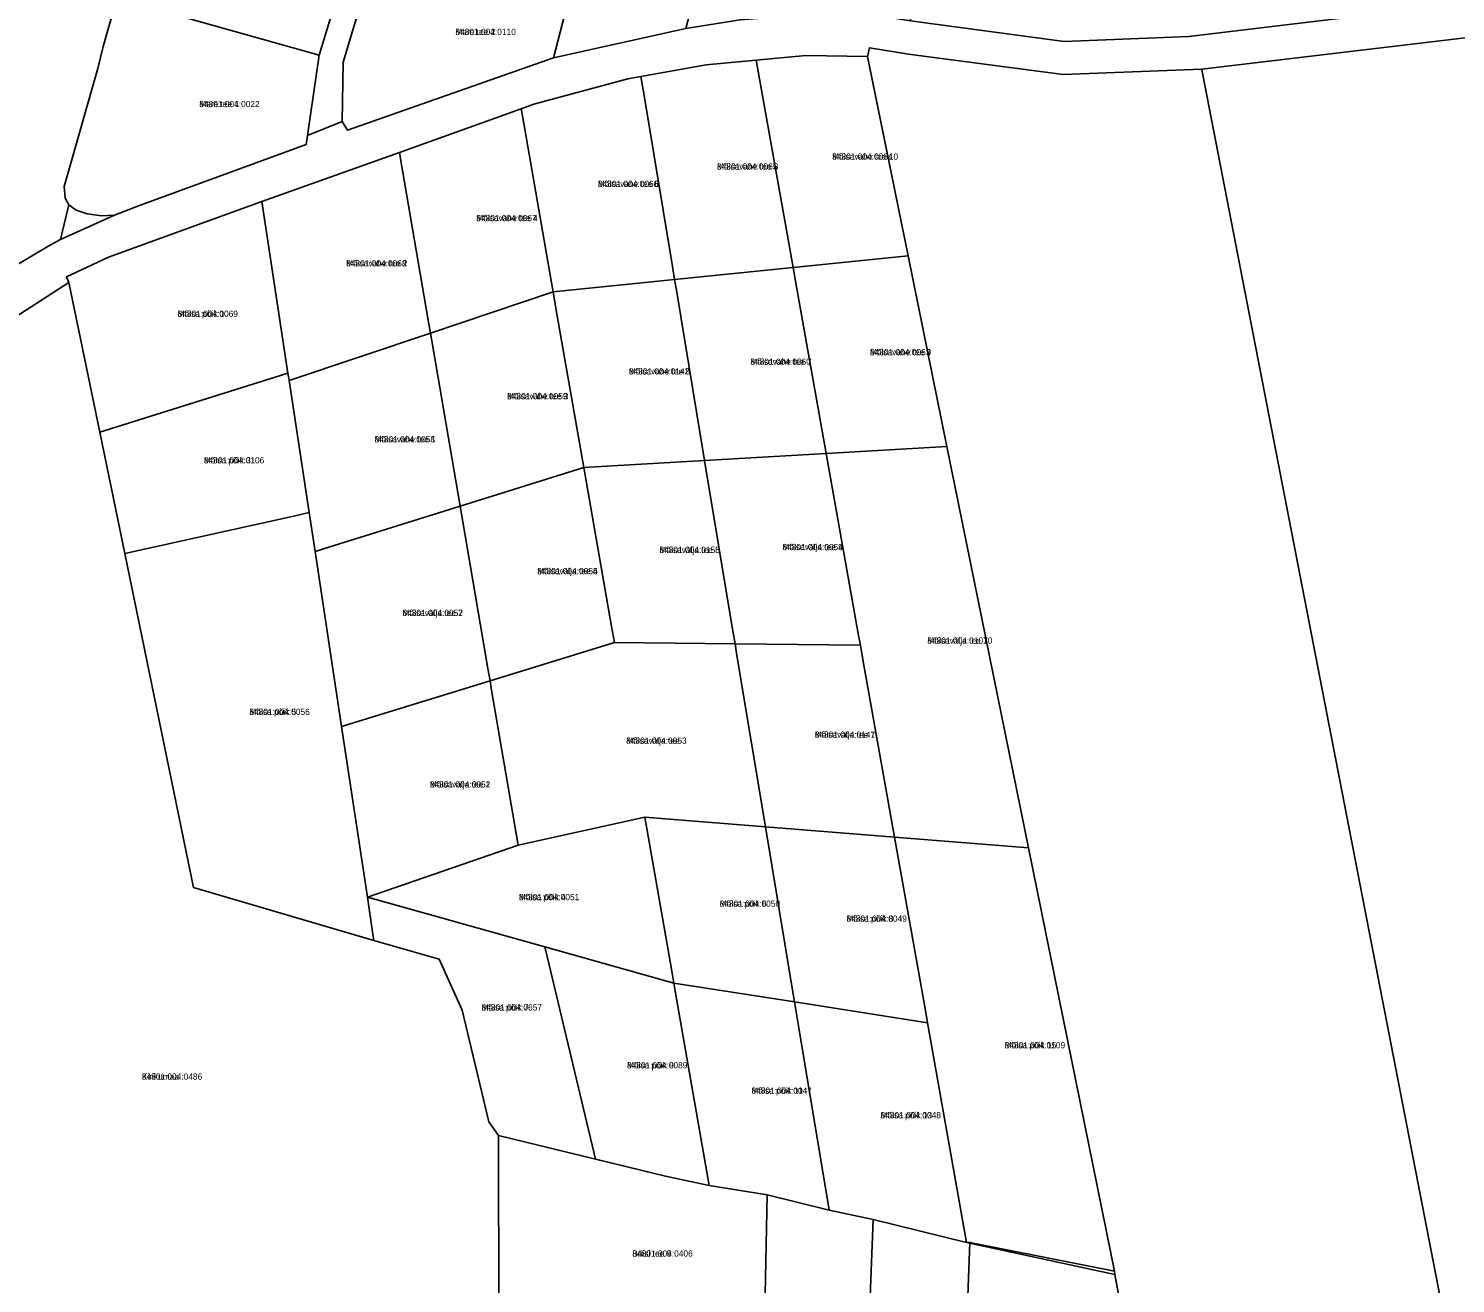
# Model space of a CAD drawing. Extents: x 520985 to 542706, y 6413723 to 6468993.
# Drawn here: x 528345 to 528687.6, y 6455911.2 to 6456212.7 of the extents above; entities that cross this region are included whole.
import ezdxf

# ---------------------------------------------------------------- set-up
doc = ezdxf.new("R2010")
doc.units = 0
for name, color, linetype in [('L_AADRESS', 7, 'Continuous'), ('PIIR', 7, 'Continuous'), ('TUNNUS', 7, 'Continuous')]:
    doc.layers.add(name, color=color, linetype=linetype)

msp = doc.modelspace()

# ---------------------------------------------------------------- linework, layer by layer
at = {"layer": 'PIIR'}
for points in [[(528556.88, 6456216.98), (528558.68, 6456259.93), (528619.9, 6456257.99), (528624.94, 6456257.83), (528679.22, 6456448.72), (528737.44, 6456454.64), (528782.62, 6456232.25), (528783.08, 6456229.98), (528623.6, 6456210.72), (528593.64, 6456209.59), (528556.78, 6456214.48)], [(528516.48, 6456264.57), (528503.27, 6456214.54), (528502.79, 6456212.71), (528471.03, 6456205.61), (528471.51, 6456207.45), (528474.91, 6456220.55), (528481.64, 6456246.71), (528488.41, 6456272.88)], [(528366.21, 6456219.91), (528372.01, 6456242.17), (528373.83, 6456241.69), (528421.37, 6456228.24), (528414.79, 6456206.25), (528367.66, 6456219.53)], [(528474.91, 6456220.55), (528471.51, 6456207.45), (528471.03, 6456205.61), (528421.58, 6456188.22), (528420.26, 6456190.35), (528420.55, 6456204.62), (528429.36, 6456234)], [(528367.66, 6456219.53), (528414.79, 6456206.25), (528411.94, 6456186.98), (528411.61, 6456184.79), (528371.6, 6456170.12), (528365.61, 6456167.8), (528362.48, 6456167.65), (528359.04, 6456168.19), (528356.38, 6456169.07), (528354.63, 6456170.34), (528353.76, 6456171.88), (528353.55, 6456174.72), (528361.65, 6456203.1), (528362.91, 6456208.35), (528366.21, 6456219.91)], [(528704.77, 6456212.22), (528705.38, 6456209.19), (528941.94, 6455028.97), (528863.78, 6455010.13), (528766.34, 6455483.52), (528702.03, 6455814.63), (528626.9, 6456201.95), (528626.71, 6456202.92)], [(528499.59, 6456155.52), (528492.86, 6456196.14), (528492.03, 6456201.17), (528507.69, 6456203.91), (528519.72, 6456205.07), (528528.18, 6456157.49), (528528.58, 6456155.26), (528500.12, 6456152.4)], [(528528.18, 6456157.49), (528519.72, 6456205.07), (528531.66, 6456206.22), (528546.44, 6456205.97), (528546.76, 6456204.37), (528556.18, 6456158.05), (528528.58, 6456155.26)], [(528470.4, 6456152.55), (528463.56, 6456191.69), (528463.26, 6456193.41), (528466.32, 6456194.49), (528488.85, 6456200.62), (528492.03, 6456201.17), (528492.86, 6456196.14), (528499.59, 6456155.52), (528500.12, 6456152.4), (528470.93, 6456149.45)], [(528440.94, 6456142.63), (528434.31, 6456181.37), (528434.05, 6456182.92), (528463.26, 6456193.41), (528463.56, 6456191.69), (528470.4, 6456152.55), (528470.93, 6456149.45), (528441.48, 6456139.52)], [(528407.26, 6456129.84), (528401, 6456171.1), (528434.05, 6456182.92), (528434.31, 6456181.37), (528440.94, 6456142.63), (528441.48, 6456139.52), (528407.54, 6456128.08)], [(528354.05, 6456153.01), (528364.19, 6456157.74), (528401, 6456171.1), (528407.26, 6456129.84), (528404.18, 6456128.89), (528362.06, 6456115.69), (528354.61, 6456151.67)], [(528529.16, 6456152.01), (528528.58, 6456155.26), (528556.18, 6456158.05), (528565.46, 6456112.29), (528536.53, 6456110.6)], [(528500.62, 6456149.36), (528500.12, 6456152.4), (528528.58, 6456155.26), (528529.16, 6456152.01), (528536.53, 6456110.6), (528507.33, 6456108.9)], [(528354.61, 6456151.67), (528362.06, 6456115.69), (528368.09, 6456086.54), (528384.57, 6456006.27), (528427.91, 6455993.57), (528434.62, 6455991.69), (528443.55, 6455989.09), (528449.1, 6455976.87), (528455.47, 6455949.99), (528457.82, 6455946.69), (528457.9, 6455903.07), (528449.98, 6455902.56), (528432.93, 6455887.74), (528435.26, 6455864.87), (528344.52, 6455848.73), (528318.55, 6455941.07), (528290.8, 6455984.15), (528286.46, 6456012.85), (528297.35, 6456077.01), (528306.62, 6456113.22), (528332.88, 6456137.64)], [(528471.71, 6456145.01), (528470.93, 6456149.45), (528500.12, 6456152.4), (528500.62, 6456149.36), (528507.33, 6456108.9), (528478.32, 6456107.2)], [(528441.79, 6456137.67), (528441.48, 6456139.52), (528470.93, 6456149.45), (528471.71, 6456145.01), (528478.32, 6456107.2), (528448.6, 6456097.91)], [(528413.77, 6456087), (528412.35, 6456096.36), (528407.54, 6456128.08), (528441.48, 6456139.52), (528441.79, 6456137.67), (528448.6, 6456097.91), (528417.1, 6456088.05)], [(528362.06, 6456115.69), (528404.18, 6456128.89), (528407.26, 6456129.84), (528407.54, 6456128.08), (528412.35, 6456096.36), (528409.03, 6456095.63), (528368.09, 6456086.54)], [(528514.13, 6456067.88), (528507.33, 6456108.9), (528536.53, 6456110.6), (528544.31, 6456066.81), (528544.72, 6456064.49), (528514.63, 6456064.85)], [(528545.34, 6456061.06), (528544.72, 6456064.49), (528544.31, 6456066.81), (528536.53, 6456110.6), (528565.46, 6456112.29), (528585.06, 6456015.8), (528552.93, 6456018.38)], [(528455.28, 6456058.93), (528448.6, 6456097.91), (528478.32, 6456107.2), (528485, 6456068.97), (528485.66, 6456065.19), (528455.79, 6456055.96)], [(528485, 6456068.97), (528478.32, 6456107.2), (528507.33, 6456108.9), (528514.13, 6456067.88), (528514.63, 6456064.85), (528485.66, 6456065.19)], [(528368.09, 6456086.54), (528409.03, 6456095.63), (528412.35, 6456096.36), (528413.77, 6456087), (528420.15, 6456044.96), (528426.37, 6456003.99), (528427.59, 6455995.69), (528427.91, 6455993.57), (528384.57, 6456006.27)], [(528413.77, 6456087), (528417.1, 6456088.05), (528448.6, 6456097.91), (528455.28, 6456058.93), (528455.79, 6456055.96), (528420.15, 6456044.96)], [(528462.55, 6456016.49), (528456.17, 6456053.75), (528455.79, 6456055.96), (528485.66, 6456065.19), (528514.63, 6456064.85), (528515.09, 6456062.08), (528521.92, 6456020.89), (528492.99, 6456023.21)], [(528515.09, 6456062.08), (528514.63, 6456064.85), (528544.72, 6456064.49), (528545.34, 6456061.06), (528552.93, 6456018.38), (528521.92, 6456020.89)], [(528420.15, 6456044.96), (528455.79, 6456055.96), (528456.17, 6456053.75), (528462.55, 6456016.49), (528426.37, 6456003.99)], [(528426.37, 6456003.99), (528462.55, 6456016.49), (528492.99, 6456023.21), (528499.36, 6455986.67), (528499.96, 6455983.31), (528468.94, 6455992.03)], [(528499.36, 6455986.67), (528492.99, 6456023.21), (528521.92, 6456020.89), (528528.42, 6455981.62), (528528.9, 6455978.8), (528499.96, 6455983.31)], [(528528.42, 6455981.62), (528521.92, 6456020.89), (528552.93, 6456018.38), (528560.33, 6455976.76), (528560.86, 6455973.82), (528528.9, 6455978.8)], [(528561.42, 6455970.65), (528560.86, 6455973.82), (528560.33, 6455976.76), (528552.93, 6456018.38), (528585.06, 6456015.8), (528605.71, 6455914.15), (528605.84, 6455913.35), (528570.24, 6455921.03)], [(528427.91, 6455993.57), (528427.59, 6455995.69), (528426.37, 6456003.99), (528468.94, 6455992.03), (528469.96, 6455987.75), (528481.15, 6455941.03), (528457.82, 6455946.69), (528455.47, 6455949.99), (528449.1, 6455976.87), (528443.55, 6455989.09), (528434.62, 6455991.69)], [(528469.96, 6455987.75), (528468.94, 6455992.03), (528499.96, 6455983.31), (528500.52, 6455980.06), (528508.43, 6455934.75), (528497.9, 6455936.96), (528481.15, 6455941.03)], [(528500.52, 6455980.06), (528499.96, 6455983.31), (528528.9, 6455978.8), (528529.85, 6455973.07), (528537.2, 6455928.81), (528522.34, 6455932.47), (528508.43, 6455934.75)], [(528529.85, 6455973.07), (528528.9, 6455978.8), (528560.86, 6455973.82), (528561.42, 6455970.65), (528570.24, 6455921.03), (528547.78, 6455926.57), (528537.2, 6455928.81)], [(528457.9, 6455903.07), (528457.82, 6455946.69), (528497.9, 6455936.96), (528508.43, 6455934.75), (528522.34, 6455932.47), (528521.5, 6455888.57), (528489.94, 6455896.19), (528495.51, 6455900.01), (528457.54, 6455896.38)], [(528522.34, 6455932.47), (528537.2, 6455928.81), (528547.78, 6455926.57), (528546.22, 6455885.38), (528546.16, 6455882.61), (528521.5, 6455888.57)], [(528546.22, 6455885.38), (528547.78, 6455926.57), (528570.24, 6455921.03), (528571.04, 6455921.03), (528569.48, 6455880.17), (528569.37, 6455877.01), (528546.16, 6455882.61)], [(528569.48, 6455880.17), (528571.04, 6455921.03), (528605.71, 6455914.15), (528605.84, 6455913.35), (528613.36, 6455872.62), (528602.62, 6455868.45), (528569.37, 6455877.01)]]:
    msp.add_lwpolyline(points, close=True, dxfattribs=at)
for points in [[(528332.39, 6456427.51), (528346.26, 6456438.94), (528350.84, 6456443.58), (528378.98, 6456440.23), (528426.76, 6456436.25), (528422.57, 6456420.37), (528415, 6456398.29), (528408.84, 6456375.95), (528402.38, 6456353.05), (528396.24, 6456330.97), (528390.05, 6456308.8), (528384.02, 6456286.64), (528378.05, 6456264.38), (528372.01, 6456242.17), (528366.21, 6456219.91), (528362.91, 6456208.35), (528361.65, 6456203.1), (528353.55, 6456174.72), (528353.76, 6456171.88), (528354.63, 6456170.34), (528352.95, 6456163.36), (528352.62, 6456161.99), (528349.83, 6456160.45), (528325.56, 6456146.03)], [(528429.36, 6456234), (528420.55, 6456204.62), (528420.26, 6456190.35), (528411.94, 6456186.98), (528414.79, 6456206.25), (528421.37, 6456228.24)], [(528325.56, 6456146.03), (528349.83, 6456160.45), (528352.62, 6456161.99), (528365.61, 6456167.8), (528371.6, 6456170.12), (528411.61, 6456184.79), (528411.94, 6456186.98), (528420.26, 6456190.35), (528421.58, 6456188.22), (528471.03, 6456205.61), (528502.79, 6456212.71), (528515.88, 6456214.73), (528530.56, 6456215.92), (528547.33, 6456216.05), (528556.78, 6456214.48), (528593.64, 6456209.59), (528623.6, 6456210.72), (528783.08, 6456229.98)], [(528704.77, 6456212.22), (528626.71, 6456202.92), (528593.46, 6456201.59), (528556.29, 6456206.49), (528546.93, 6456208.06), (528546.44, 6456205.97), (528531.66, 6456206.22), (528519.72, 6456205.07), (528507.69, 6456203.91), (528492.03, 6456201.17), (528488.85, 6456200.62), (528466.32, 6456194.49), (528463.26, 6456193.41), (528434.05, 6456182.92), (528401, 6456171.1), (528364.19, 6456157.74), (528354.05, 6456153.01), (528354.61, 6456151.67), (528332.88, 6456137.64)], [(528707.1, 6455390.67), (528686.98, 6455494.08), (528660.97, 6455641.91), (528655.59, 6455644.1), (528653.16, 6455656.86), (528648.4, 6455684.42), (528644.35, 6455705.04), (528639.68, 6455728.92), (528634.52, 6455756.2), (528619.74, 6455837.43), (528613.36, 6455872.62), (528605.84, 6455913.35), (528605.71, 6455914.15), (528585.06, 6456015.8), (528565.46, 6456112.29), (528556.18, 6456158.05), (528546.44, 6456205.97), (528546.93, 6456208.06), (528556.29, 6456206.49), (528593.46, 6456201.59), (528626.71, 6456202.92), (528626.9, 6456201.95), (528702.03, 6455814.63)]]:
    msp.add_lwpolyline(points, dxfattribs=at)

# ---------------------------------------------------------------- texts
at = {"layer": 'L_AADRESS'}
for s, p in [('Mere tee 2', (528447.48, 6456211.11)), ('Mere tee 1', (528385.97, 6456193.78)), ('Mõisavahe tee 10', (528537.95, 6456181.16)), ('Mõisavahe tee 8', (528510.3, 6456178.79)), ('Mõisavahe tee 6', (528481.69, 6456174.6)), ('Mõisavahe tee 4', (528452.49, 6456166.39)), ('Mõisavahe tee 2', (528421.24, 6456155.52)), ('Mõisa põik 1', (528380.76, 6456143.4)), ('Mõisavahe tee 7', (528518.32, 6456131.88)), ('Mõisavahe tee 9', (528547.02, 6456134.17)), ('Mõisavahe tee 5', (528489.13, 6456129.56)), ('Mõisavahe tee 3', (528459.9, 6456123.59)), ('Mõisavahe tee 1', (528428.07, 6456113.24)), ('Mõisa põik 3', (528387.08, 6456108.19)), ('Mõisavälja tee 8', (528526.02, 6456087.35)), ('Mõisavälja tee 6', (528496.48, 6456086.66)), ('Mõisavälja tee 4', (528467.13, 6456081.58)), ('Mõisavälja tee 2', (528434.78, 6456071.53)), ('Mõisavälja tee 10', (528560.8, 6456064.88)), ('Mõisa põik 5', (528398, 6456047.76)), ('Mõisavälja tee 3', (528488.5, 6456040.84)), ('Mõisavälja tee 7', (528533.78, 6456042.28)), ('Mõisavälja tee 1', (528441.35, 6456030.33)), ('Mõisa põik 4', (528462.72, 6456003.26)), ('Mõisa põik 6', (528510.95, 6456001.68)), ('Mõisa põik 8', (528541.39, 6455998.08)), ('Mõisa põik 7', (528453.76, 6455976.75)), ('Mõisa põik 15', (528579.39, 6455967.66)), ('Mõisa põik 9', (528488.68, 6455962.84)), ('Kirikumaa', (528372.18, 6455960.13)), ('Mõisa põik 11', (528518.58, 6455956.75)), ('Mõisa põik 13', (528549.57, 6455950.85)), ('Briisi tee 9', (528489.96, 6455917.63))]:
    msp.add_text(s, height=1.5, dxfattribs=at).set_placement(p)
at = {"layer": 'TUNNUS'}
for s, p in [('84801:004:0110', (528447.48, 6456211.11)), ('84801:004:0022', (528385.97, 6456193.78)), ('84801:004:0064', (528537.95, 6456181.16)), ('84801:004:0065', (528510.3, 6456178.79)), ('84801:004:0066', (528481.69, 6456174.6)), ('84801:004:0067', (528452.49, 6456166.39)), ('84801:004:0068', (528421.24, 6456155.52)), ('84801:004:0069', (528380.76, 6456143.4)), ('84801:004:0060', (528518.32, 6456131.88)), ('84801:004:0063', (528547.02, 6456134.17)), ('84801:004:0142', (528489.13, 6456129.56)), ('84801:004:0059', (528459.9, 6456123.59)), ('84801:004:0058', (528428.07, 6456113.24)), ('84801:004:0106', (528387.08, 6456108.19)), ('84801:004:0054', (528526.02, 6456087.35)), ('84801:004:0155', (528496.48, 6456086.66)), ('84801:004:0055', (528467.13, 6456081.58)), ('84801:004:0057', (528434.78, 6456071.53)), ('84801:004:0107', (528560.8, 6456064.88)), ('84801:004:0056', (528398, 6456047.76)), ('84801:004:0053', (528488.5, 6456040.84)), ('84801:004:0141', (528533.78, 6456042.28)), ('84801:004:0052', (528441.35, 6456030.33)), ('84801:004:0051', (528462.72, 6456003.26)), ('84801:004:0050', (528510.95, 6456001.68)), ('84801:004:0049', (528541.39, 6455998.08)), ('84801:004:0657', (528453.76, 6455976.75)), ('84801:004:0109', (528579.39, 6455967.66)), ('84801:004:0089', (528488.68, 6455962.84)), ('84801:004:0486', (528372.18, 6455960.13)), ('84801:004:0047', (528518.58, 6455956.75)), ('84801:004:0048', (528549.57, 6455950.85)), ('84801:004:0406', (528489.96, 6455917.63))]:
    msp.add_text(s, height=1.5, dxfattribs=at).set_placement(p)

doc.saveas('drawing.dxf')
